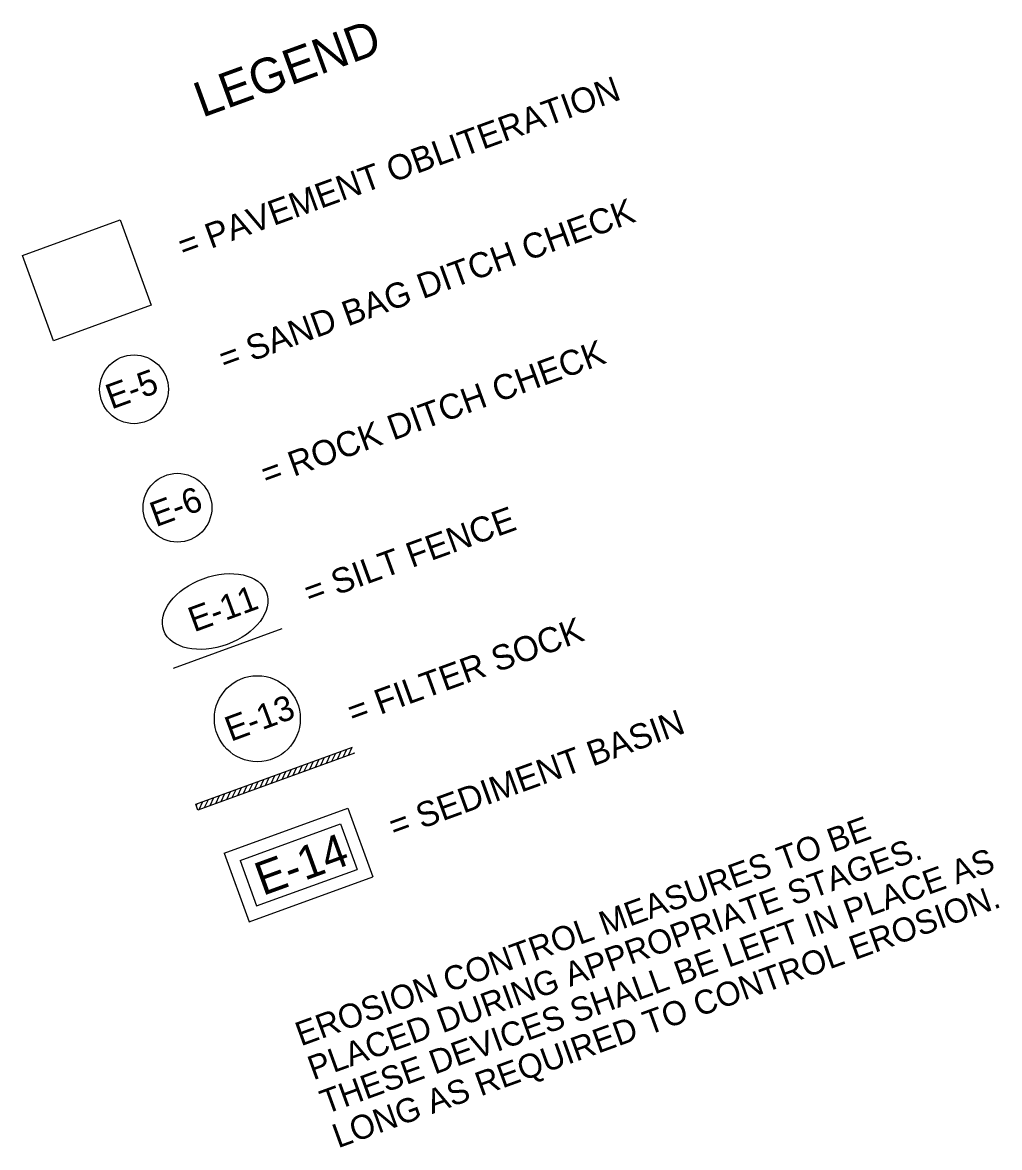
# Model space of a CAD drawing. Extents: x 1710782 to 1712392, y 548480 to 549912.
# Drawn here: x 1710881.8 to 1711116.4, y 548480 to 548750.1 of the extents above; entities that cross this region are included whole.
import ezdxf

# ---------------------------------------------------------------- set-up
doc = ezdxf.new("R2010")
doc.units = 0
doc.layers.add('R_Contour Annot', color=7, linetype='Continuous')
doc.layers.add('R_Proposed Const Limits_Fill', color=7, linetype='Continuous')

msp = doc.modelspace()

# ---------------------------------------------------------------- linework, layer by layer
at = {"layer": 'R_Contour Annot'}
msp.add_lwpolyline([(1710881.83, 548694.16), (1710905.27, 548702.69), (1710912.72, 548682.22), (1710889.28, 548673.69)], close=True, dxfattribs=at)
at = {"layer": 'R_Proposed Const Limits_Fill'}
for p, q in [((1710923.44, 548562.43), (1710961.03, 548576.11)), ((1710961.55, 548574.7), (1710923.96, 548561.02)), ((1710954.8, 548572.25), (1710955.7, 548574.17)), ((1710956.13, 548572.73), (1710957.03, 548574.66)), ((1710957.46, 548573.22), (1710958.36, 548575.14)), ((1710958.79, 548573.7), (1710959.69, 548575.62)), ((1710960.12, 548574.18), (1710961.02, 548576.11)), ((1710961.45, 548574.67), (1710961.51, 548574.8)), ((1710948.16, 548569.83), (1710949.06, 548571.75)), ((1710949.49, 548570.31), (1710950.39, 548572.24)), ((1710950.82, 548570.8), (1710951.71, 548572.72)), ((1710952.15, 548571.28), (1710953.04, 548573.2)), ((1710953.48, 548571.77), (1710954.37, 548573.69)), ((1710940.19, 548566.93), (1710941.08, 548568.85)), ((1710941.52, 548567.41), (1710942.41, 548569.33)), ((1710942.84, 548567.9), (1710943.74, 548569.82)), ((1710944.17, 548568.38), (1710945.07, 548570.3)), ((1710945.5, 548568.86), (1710946.4, 548570.79)), ((1710946.83, 548569.35), (1710947.73, 548571.27)), ((1710933.54, 548564.51), (1710934.44, 548566.43)), ((1710934.87, 548564.99), (1710935.77, 548566.92)), ((1710936.2, 548565.48), (1710937.1, 548567.4)), ((1710937.53, 548565.96), (1710938.42, 548567.88)), ((1710938.86, 548566.44), (1710939.75, 548568.37)), ((1710925.57, 548561.61), (1710926.46, 548563.53)), ((1710926.9, 548562.09), (1710927.79, 548564.01)), ((1710928.23, 548562.58), (1710929.12, 548564.5)), ((1710929.55, 548563.06), (1710930.45, 548564.98)), ((1710930.88, 548563.54), (1710931.78, 548565.47)), ((1710932.21, 548564.03), (1710933.11, 548565.95)), ((1710923.96, 548561.02), (1710923.44, 548562.43)), ((1710923.58, 548562.07), (1710923.81, 548562.56)), ((1710924.24, 548561.12), (1710925.14, 548563.05)), ((1710930.28, 548550.66), (1710959.97, 548561.46)), ((1710959.97, 548561.46), (1710965.97, 548544.99)), ((1710934.07, 548548.89), (1710958.2, 548557.67)), ((1710958.2, 548557.67), (1710962.17, 548546.76)), ((1710930.28, 548550.66), (1710936.27, 548534.19)), ((1710934.07, 548548.89), (1710938.04, 548537.99)), ((1710936.27, 548534.19), (1710965.97, 548544.99)), ((1710938.04, 548537.99), (1710962.17, 548546.76))]:
    msp.add_line(p, q, dxfattribs=at)
msp.add_lwpolyline([(1710918.07, 548595.04), (1710944.19, 548604.56)], dxfattribs=at)
for centre, radius in [((1710908.61, 548662.02), 8.26), ((1710919.04, 548633.59), 8.26), ((1710938.22, 548582.94), 10.32)]:
    msp.add_circle(centre, radius, dxfattribs=at)
msp.add_ellipse((1710928.1, 548608.67), major_axis=(12.34, 4.54), ratio=0.638788, dxfattribs=at)

# ---------------------------------------------------------------- texts
for s, height, rotation, p in [('LEGEND', 8.439, 20, (1710924.99, 548727.19)), ('= PAVEMENT OBLITERATION', 6, 20, (1710920.52, 548693.35)), ('= SAND BAG DITCH CHECK', 6, 20, (1710930.36, 548666.32)), ('= ROCK DITCH CHECK', 6, 20, (1710940.44, 548638.62)), ('E-5 ', 5.999, 20, (1710903.19, 548657.14)), ('E-6 ', 5.999, 20.4005, (1710913.85, 548628.88)), ('= SILT FENCE', 6, 20, (1710950.78, 548610.19)), ('E-11', 5.999, 20.2144, (1710923.02, 548603.65)), ('= FILTER SOCK', 6, 20, (1710961.19, 548581.48)), ('E-13', 5.999, 20.4005, (1710931.85, 548577.37)), ('= SEDIMENT BASIN', 6, 20, (1710971.15, 548554.11)), ('EROSION CONTROL MEASURES TO BE', 5.7688, 20, (1710948.68, 548504.27)), ('E-14', 8.001, 19.9884, (1710939.52, 548540.37)), ('PLACED DURING APPROPRIATE STAGES. ', 5.7688, 20, (1710951.65, 548496.11)), ('THESE DEVICES SHALL BE LEFT IN PLACE AS ', 5.7688, 20, (1710954.62, 548487.95)), ('LONG AS REQUIRED TO CONTROL EROSION.', 5.7688, 20, (1710957.59, 548479.79))]:
    msp.add_text(s, height=height, rotation=rotation, dxfattribs=at).set_placement(p)

doc.saveas('drawing.dxf')
